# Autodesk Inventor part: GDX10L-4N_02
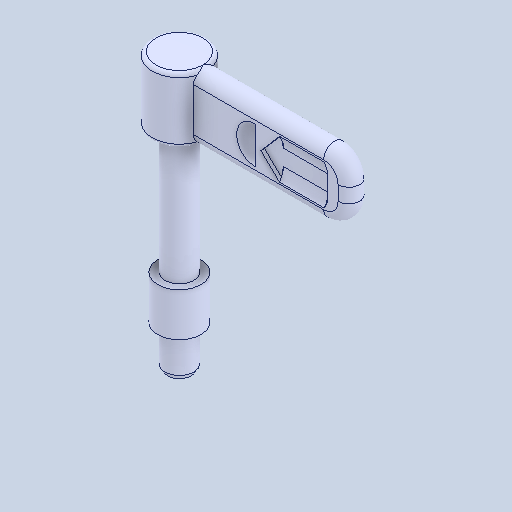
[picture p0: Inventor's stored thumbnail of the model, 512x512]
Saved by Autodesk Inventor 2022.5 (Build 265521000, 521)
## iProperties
Created: 2024-06
Part Number: GDX10L-4N_02
Material: 一般
Document SubType Name: Modeling
Designer: ImaoCorp
Density: 1 g/cm^3
Appearance: 既定
Author: ImaoCorp
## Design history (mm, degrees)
feature "GDX10L-4N_02"
node "ソリッド1"
